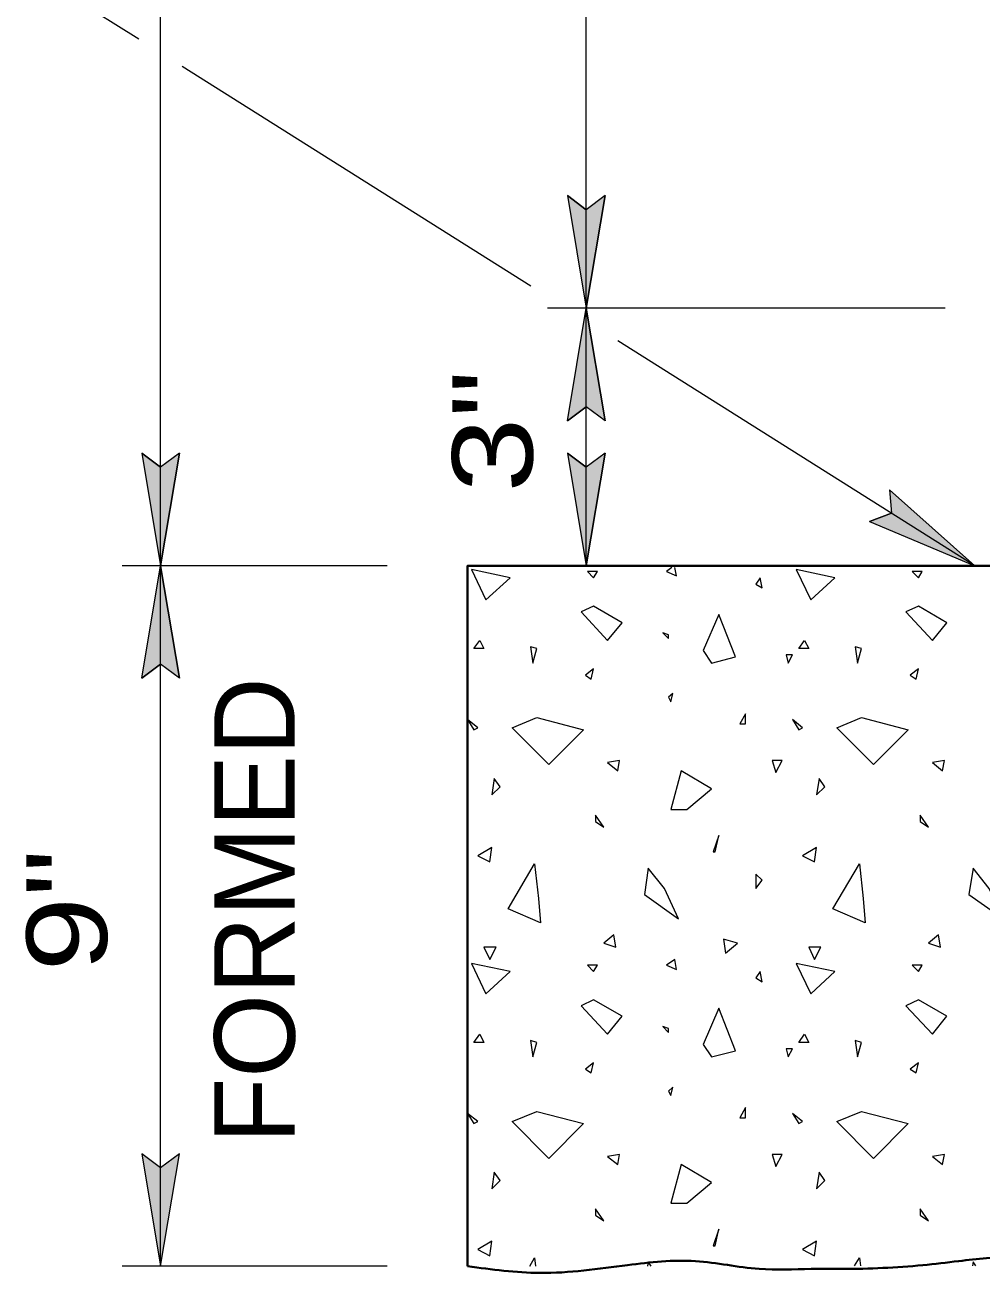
# Model space of a CAD drawing. Extents: x -9.07 to -2.08, y 8.04 to 17.77.
# Drawn here: x -7.557 to -6.844, y 13.756 to 14.699 of the extents above; entities that cross this region are included whole.
import ezdxf
from ezdxf.enums import TextEntityAlignment as Align

# ---------------------------------------------------------------- set-up
doc = ezdxf.new("R2010")
doc.units = 0
doc.header["$LTSCALE"] = 0.024
for name, color, linetype, lineweight in [('1', 7, 'Continuous', 35), ('10', 7, 'Continuous', 13), ('12', 7, 'Continuous', 53), ('6', 7, 'Continuous', 13)]:
    doc.layers.add(name, color=color, linetype=linetype, lineweight=lineweight)

msp = doc.modelspace()

# ---------------------------------------------------------------- hatches: boundary and pattern name
at = {"layer": '10'}
for points in [[(-7.1385, 14.48783), (-7.1245, 14.57183), (-7.1385, 14.56133), (-7.1525, 14.57183)], [(-7.1385, 14.48783), (-7.1245, 14.40383), (-7.1385, 14.41433), (-7.1525, 14.40383)], [(-7.456, 14.29567), (-7.442, 14.37967), (-7.456, 14.36917), (-7.47, 14.37967)], [(-7.1385, 14.29567), (-7.1245, 14.37967), (-7.1385, 14.36917), (-7.1525, 14.37967)], [(-6.84867, 14.29567), (-6.91233, 14.35233), (-6.91083, 14.33483), (-6.92733, 14.32867)], [(-7.456, 14.29567), (-7.442, 14.21167), (-7.456, 14.22217), (-7.47, 14.21167)], [(-7.456, 13.773), (-7.442, 13.857), (-7.456, 13.8465), (-7.47, 13.857)]]:
    msp.add_hatch(color=256, dxfattribs=at).paths.add_polyline_path(points)

# ---------------------------------------------------------------- linework, layer by layer
at = {"layer": '1'}
msp.add_lwpolyline([(-7.227, 13.773), (-7.227, 14.29567), (-6.81067, 14.29567), (-6.81067, 14.48783), (-6.4615, 14.98667)], dxfattribs=at)
at = {"layer": '10'}
for p, q in [((-7.456, 14.29567), (-7.456, 16.42933)), ((-7.1385, 14.48783), (-7.1385, 15.14883)), ((-7.47233, 14.68867), (-7.54067, 14.73167)), ((-7.17983, 14.50433), (-7.43983, 14.66817)), ((-7.1525, 14.57183), (-7.1385, 14.48783)), ((-7.1525, 14.57183), (-7.1385, 14.56133)), ((-7.1245, 14.57183), (-7.1385, 14.48783)), ((-7.1245, 14.57183), (-7.1385, 14.56133)), ((-6.87067, 14.48783), (-7.16733, 14.48783)), ((-7.1525, 14.40383), (-7.1385, 14.48783)), ((-7.1385, 14.29567), (-7.1385, 14.48783)), ((-7.1245, 14.40383), (-7.1385, 14.48783)), ((-6.84867, 14.29567), (-7.115, 14.4635)), ((-7.1525, 14.40383), (-7.1385, 14.41433)), ((-7.1245, 14.40383), (-7.1385, 14.41433)), ((-7.47, 14.37967), (-7.456, 14.29567)), ((-7.47, 14.37967), (-7.456, 14.36917)), ((-7.442, 14.37967), (-7.456, 14.29567)), ((-7.442, 14.37967), (-7.456, 14.36917)), ((-7.1525, 14.37967), (-7.1385, 14.29567)), ((-7.1525, 14.37967), (-7.1385, 14.36917)), ((-7.1245, 14.37967), (-7.1385, 14.29567)), ((-7.1245, 14.37967), (-7.1385, 14.36917)), ((-6.91233, 14.35233), (-6.84867, 14.29567)), ((-6.91233, 14.35233), (-6.91083, 14.33483)), ((-6.92733, 14.32867), (-6.91083, 14.33483)), ((-6.92733, 14.32867), (-6.84867, 14.29567)), ((-7.287, 14.29567), (-7.48483, 14.29567)), ((-7.47, 14.21167), (-7.456, 14.29567)), ((-7.442, 14.21167), (-7.456, 14.29567)), ((-7.456, 13.773), (-7.456, 14.29567)), ((-7.47, 14.21167), (-7.456, 14.22217)), ((-7.442, 14.21167), (-7.456, 14.22217)), ((-7.287, 13.773), (-7.48483, 13.773))]:
    msp.add_line(p, q, dxfattribs=at)
for points in [[(-7.1385, 14.48783), (-7.1245, 14.57183), (-7.1385, 14.56133), (-7.1525, 14.57183)], [(-7.1385, 14.48783), (-7.1245, 14.40383), (-7.1385, 14.41433), (-7.1525, 14.40383)], [(-7.456, 14.29567), (-7.442, 14.37967), (-7.456, 14.36917), (-7.47, 14.37967)], [(-7.1385, 14.29567), (-7.1245, 14.37967), (-7.1385, 14.36917), (-7.1525, 14.37967)], [(-6.84867, 14.29567), (-6.91233, 14.35233), (-6.91083, 14.33483), (-6.92733, 14.32867)], [(-7.456, 14.29567), (-7.442, 14.21167), (-7.456, 14.22217), (-7.47, 14.21167)], [(-7.456, 13.773), (-7.442, 13.857), (-7.456, 13.8465), (-7.47, 13.857)]]:
    msp.add_lwpolyline(points, close=True, dxfattribs=at)
at = {"layer": '10', "lineweight": 35}
msp.add_spline([(-7.227, 13.773), (-7.173, 13.768), (-7.10767, 13.77383), (-7.057, 13.77683), (-7.0095, 13.771), (-6.97083, 13.771), (-6.947, 13.771), (-6.8875, 13.77383), (-6.86067, 13.77683), (-6.819, 13.77983), (-6.7745, 13.77683), (-6.72683, 13.77383), (-6.68233, 13.771), (-6.64367, 13.77683), (-6.56917, 13.77683), (-6.49783, 13.78283), (-6.4205, 13.78867), (-6.364, 13.78283), (-6.29267, 13.77383), (-6.23017, 13.771), (-6.144, 13.768), (-6.04883, 13.771), (-5.9685, 13.77983), (-5.897, 13.78867), (-5.79, 13.78283), (-5.70967, 13.771), (-5.6085, 13.765), (-5.53717, 13.765), (-5.4895, 13.768), (-5.436, 13.77983), (-5.3855, 13.78867), (-5.323, 13.78867), (-5.2725, 13.77983), (-5.23083, 13.77383), (-5.16533, 13.765), (-5.094, 13.762), (-4.99883, 13.77683), (-4.94533, 13.78283), (-4.88883, 13.78283), (-4.84417, 13.77683), (-4.82333, 13.77383), (-4.78083, 13.75633), (-4.8115, 13.771)], degree=3, dxfattribs=at)
at = {"layer": '6'}
for points in [[(-7.22417, 14.29283), (-7.21333, 14.27017), (-7.19533, 14.28667)], [(-6.98183, 14.29283), (-6.971, 14.27017), (-6.953, 14.28667)], [(-7.13767, 14.29133), (-7.133, 14.28667), (-7.13017, 14.29133)], [(-7.012, 14.282), (-7.00733, 14.27917), (-7.00883, 14.28667)], [(-6.89533, 14.29133), (-6.89067, 14.28667), (-6.88783, 14.29133)], [(-7.14233, 14.26117), (-7.12267, 14.24), (-7.11183, 14.25317), (-7.133, 14.2655)], [(-6.90017, 14.26117), (-6.88033, 14.24), (-6.8695, 14.25317), (-6.89067, 14.2655)], [(-7.04517, 14.223), (-7.02717, 14.22767), (-7.0395, 14.25933), (-7.05133, 14.23233)], [(-7.07717, 14.24417), (-7.0815, 14.24567), (-7.07717, 14.24133)], [(-7.218, 14.24), (-7.21483, 14.23383), (-7.22233, 14.23383)], [(-7.18017, 14.23517), (-7.17833, 14.223), (-7.1755, 14.23383)], [(-6.97567, 14.24), (-6.9725, 14.23383), (-6.98, 14.23383)], [(-6.93783, 14.23517), (-6.93617, 14.223), (-6.93317, 14.23383)], [(-6.98933, 14.22917), (-6.988, 14.223), (-6.98467, 14.22917)], [(-7.13917, 14.214), (-7.13483, 14.21117), (-7.133, 14.21867)], [(-6.89683, 14.214), (-6.8925, 14.21117), (-6.89067, 14.21867)], [(-7.074, 14.20033), (-7.07717, 14.1975), (-7.0755, 14.19417)], [(-7.227, 14.18083), (-7.22233, 14.17333), (-7.2195, 14.17483)], [(-7.1755, 14.18233), (-7.14067, 14.17333), (-7.1665, 14.14733), (-7.19383, 14.17483)], [(-7.01967, 14.18517), (-7.024, 14.17767), (-7.01967, 14.17767)], [(-6.98, 14.17333), (-6.97717, 14.17483), (-6.98467, 14.18083)], [(-6.93317, 14.18233), (-6.89833, 14.17333), (-6.92417, 14.14733), (-6.9515, 14.17483)], [(-7.12267, 14.14883), (-7.115, 14.14267), (-7.11367, 14.15033)], [(-6.99983, 14.15033), (-6.997, 14.14133), (-6.99233, 14.15033)], [(-6.88033, 14.14883), (-6.87267, 14.14267), (-6.87133, 14.15033)], [(-7.0635, 14.11383), (-7.04517, 14.12933), (-7.06783, 14.14267), (-7.0755, 14.11383)], [(-7.20717, 14.137), (-7.209, 14.12467), (-7.20283, 14.13083)], [(-6.96483, 14.137), (-6.96667, 14.12467), (-6.9605, 14.13083)], [(-7.13167, 14.1095), (-7.13167, 14.10483), (-7.1255, 14.1005)], [(-6.88933, 14.1095), (-6.88933, 14.10483), (-6.88317, 14.1005)], [(-7.04383, 14.08217), (-7.04233, 14.08217), (-7.0395, 14.0945)], [(-7.2195, 14.07933), (-7.2105, 14.07467), (-7.209, 14.0855)], [(-6.97717, 14.07933), (-6.96817, 14.07467), (-6.96667, 14.0855)], [(-7.17417, 14.04733), (-7.17267, 14.02933), (-7.19683, 14.03967), (-7.177, 14.07317)], [(-7.09233, 14.07), (-7.09517, 14.0505), (-7.06967, 14.03217), (-7.08017, 14.05483)], [(-7.012, 14.06567), (-7.012, 14.05483), (-7.00733, 14.061)], [(-6.93183, 14.04733), (-6.93033, 14.02933), (-6.9545, 14.03967), (-6.93467, 14.07317)], [(-6.85, 14.07), (-6.853, 14.0505), (-6.82733, 14.03217), (-6.83783, 14.05483)], [(-7.118, 14.02033), (-7.1255, 14.01417), (-7.1165, 14.011)], [(-6.87567, 14.02033), (-6.88317, 14.01417), (-6.87417, 14.011)], [(-7.21483, 14.011), (-7.2105, 14.002), (-7.20583, 14.011)], [(-7.03617, 14.017), (-7.03467, 14.00667), (-7.02567, 14.01417)], [(-6.9725, 14.011), (-6.96817, 14.002), (-6.9635, 14.011)], [(-7.07867, 13.99767), (-7.07117, 13.99433), (-7.0725, 14.002)], [(-7.22417, 13.999), (-7.21333, 13.97633), (-7.19533, 13.993)], [(-7.13767, 13.99767), (-7.133, 13.993), (-7.13017, 13.99767)], [(-7.012, 13.98817), (-7.00733, 13.98533), (-7.00883, 13.993)], [(-6.98183, 13.999), (-6.971, 13.97633), (-6.953, 13.993)], [(-6.89533, 13.99767), (-6.89067, 13.993), (-6.88783, 13.99767)], [(-7.14233, 13.96733), (-7.12267, 13.94617), (-7.11183, 13.9595), (-7.133, 13.97167)], [(-6.90017, 13.96733), (-6.88033, 13.94617), (-6.8695, 13.9595), (-6.89067, 13.97167)], [(-7.04517, 13.92917), (-7.02717, 13.93383), (-7.0395, 13.9655), (-7.05133, 13.9385)], [(-7.218, 13.94617), (-7.21483, 13.94), (-7.22233, 13.94)], [(-7.07717, 13.9505), (-7.0815, 13.95183), (-7.07717, 13.9475)], [(-6.97567, 13.94617), (-6.9725, 13.94), (-6.98, 13.94)], [(-7.18017, 13.9415), (-7.17833, 13.92917), (-7.1755, 13.94)], [(-6.98933, 13.93533), (-6.988, 13.92917), (-6.98467, 13.93533)], [(-6.93783, 13.9415), (-6.93617, 13.92917), (-6.93317, 13.94)], [(-7.13917, 13.92017), (-7.13483, 13.91733), (-7.133, 13.92483)], [(-6.89683, 13.92017), (-6.8925, 13.91733), (-6.89067, 13.92483)], [(-7.074, 13.9065), (-7.07717, 13.90367), (-7.0755, 13.90033)], [(-7.227, 13.887), (-7.22233, 13.8795), (-7.2195, 13.881)], [(-7.1755, 13.8885), (-7.14067, 13.8795), (-7.1665, 13.8535), (-7.19383, 13.881)], [(-7.01967, 13.89133), (-7.024, 13.88383), (-7.01967, 13.88383)], [(-6.98, 13.8795), (-6.97717, 13.881), (-6.98467, 13.887)], [(-6.93317, 13.8885), (-6.89833, 13.8795), (-6.92417, 13.8535), (-6.9515, 13.881)], [(-7.12267, 13.855), (-7.115, 13.84883), (-7.11367, 13.8565)], [(-7.0635, 13.82017), (-7.04517, 13.8355), (-7.06783, 13.84883), (-7.0755, 13.82017)], [(-6.99983, 13.8565), (-6.997, 13.8475), (-6.99233, 13.8565)], [(-6.88033, 13.855), (-6.87267, 13.84883), (-6.87133, 13.8565)], [(-7.20717, 13.84317), (-7.209, 13.83083), (-7.20283, 13.837)], [(-6.96483, 13.84317), (-6.96667, 13.83083), (-6.9605, 13.837)], [(-7.13167, 13.81583), (-7.13167, 13.81117), (-7.1255, 13.80683)], [(-6.88933, 13.81583), (-6.88933, 13.81117), (-6.88317, 13.80683)], [(-7.04383, 13.78833), (-7.04233, 13.78833), (-7.0395, 13.80067)], [(-7.2195, 13.7855), (-7.2105, 13.78083), (-7.209, 13.79167)], [(-6.97717, 13.7855), (-6.96817, 13.78083), (-6.96667, 13.79167)]]:
    msp.add_lwpolyline(points, close=True, dxfattribs=at)
for points in [[(-7.07467, 14.29433), (-7.07867, 14.29133), (-7.07117, 14.28817), (-7.07233, 14.29433)], [(-7.18067, 13.77317), (-7.177, 13.77933), (-7.17633, 13.77317)], [(-7.09, 13.77317), (-7.09233, 13.77617), (-7.09283, 13.77317)], [(-6.93833, 13.77333), (-6.93467, 13.77933), (-6.934, 13.77333)], [(-6.84783, 13.77333), (-6.85, 13.77617), (-6.8505, 13.77333)]]:
    msp.add_lwpolyline(points, dxfattribs=at)

# ---------------------------------------------------------------- texts
at = {"layer": '12', "width": 1.25}
for s, p in [('3"', (-7.1785, 14.396)), ('9"', (-7.49608, 14.03858))]:
    msp.add_text(s, height=0.06001, rotation=90, dxfattribs=at).set_placement(p, align=Align.CENTER)
at = {"layer": '12'}
msp.add_text('FORMED', height=0.06001, rotation=90, dxfattribs=at).set_placement((-7.356, 14.03854), align=Align.CENTER)

doc.saveas('drawing.dxf')
